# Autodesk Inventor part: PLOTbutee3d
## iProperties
Author: ajt
Created: 2001-10
Part Number: PLOTbutee3d
Material: Par défaut
Document SubType Name: Proxy Part
Designer: ajt
Control State: 0
Master: False
Checked Out: False
PropertySet Name: Design Tracking Control
Shininess: 21.0
PropertySet Name: _Private Model Information
Length Units: 11269
Angle Units: 11283
Time Units: 11279
Mass Units: 11290
Length Display Precision: 3
Angle Display Precision: 2
Compacted: False
Density: 0.0
Volumn: 0.0
Area: 0.0
PropertySet Name: Model Information
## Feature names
1. LinkedPart1
